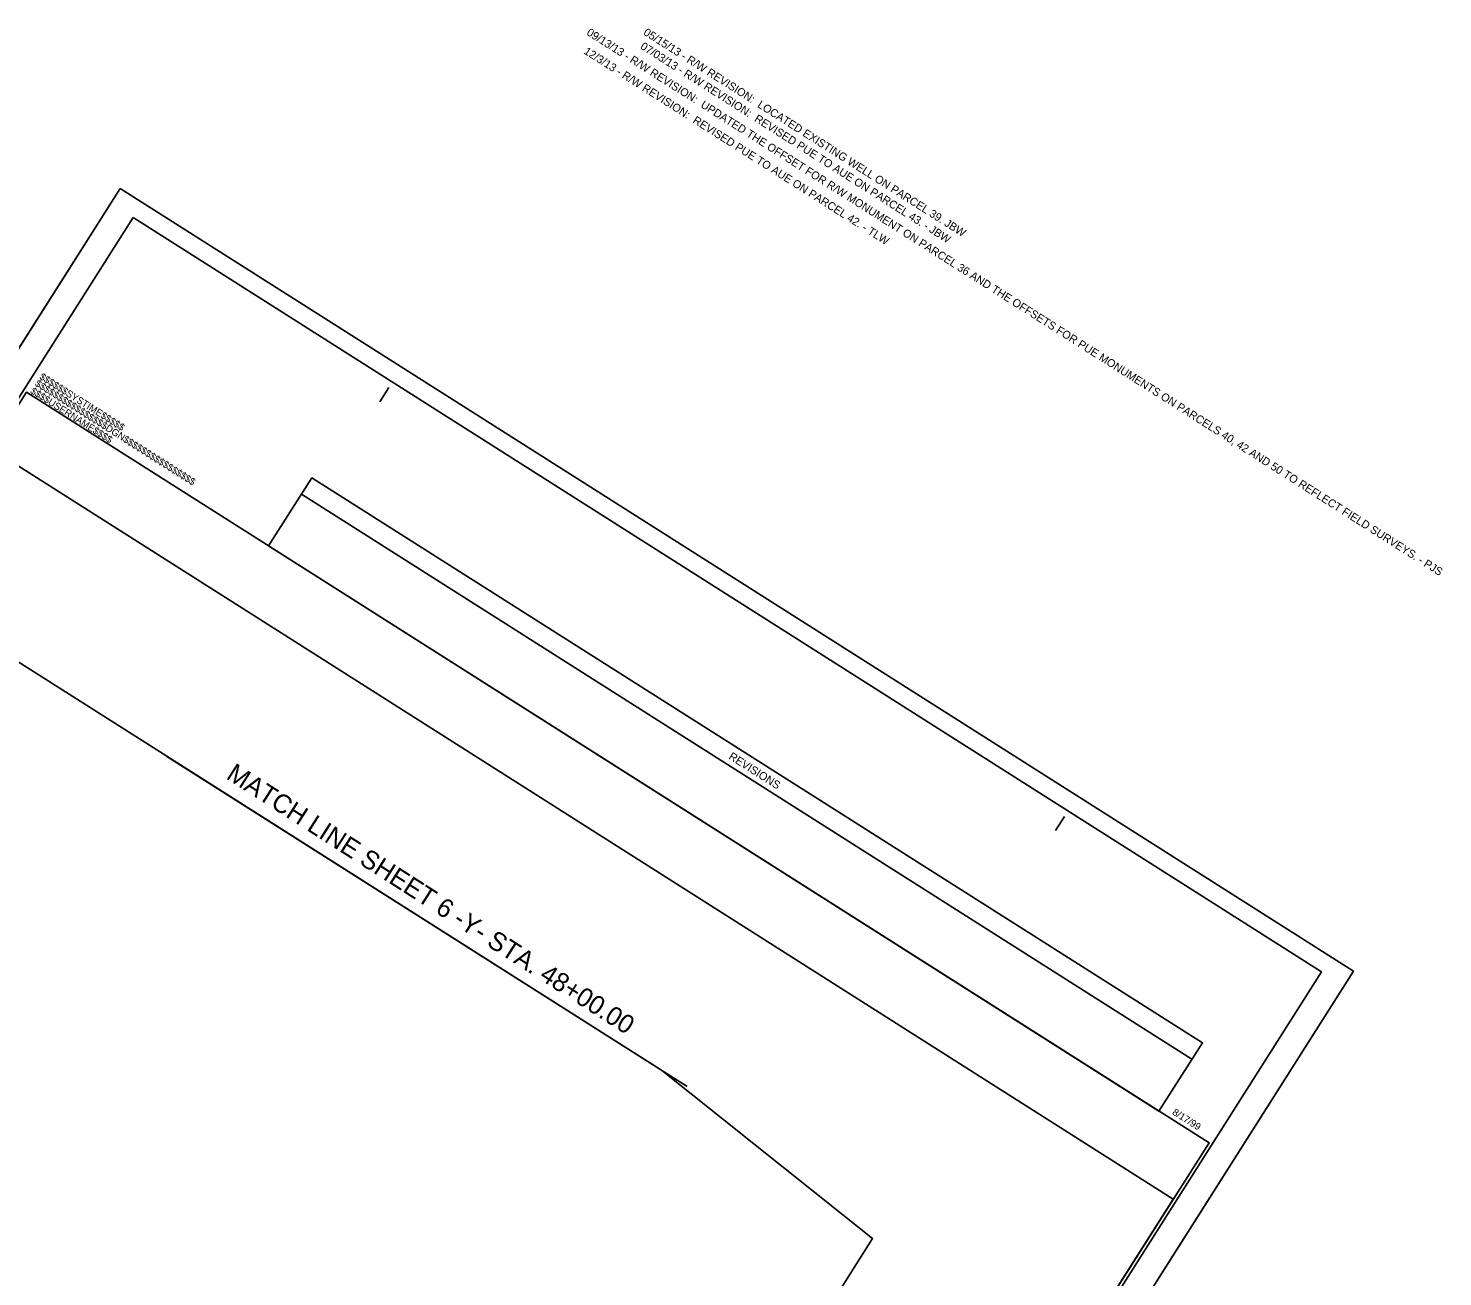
# Model space of a CAD drawing. Extents: x 1780138 to 1782093, y 811157 to 813450.
# Drawn here: x 1781033 to 1782093, y 812514 to 813450 of the extents above; entities that cross this region are included whole.
import ezdxf

# ---------------------------------------------------------------- set-up
doc = ezdxf.new("R2010")
doc.units = 0
for name, color, linetype in [('Prop Easement Aerial Utility', 7, 'Continuous'), ('Prop Easement Construction', 7, 'Continuous'), ('Prop Easement Construction Station Offsets', 7, 'Continuous'), ('Prop Easement Permanent Utility', 7, 'Continuous'), ('Prop Easement Temporary Drainage', 7, 'Continuous'), ('Prop Easement Temporary Utility', 7, 'Continuous'), ('Prop Easement Temporary Utility Station Offsets', 7, 'Continuous'), ('Prop ROW CA Lines', 7, 'Continuous'), ('Prop ROW Marker CELL', 7, 'Continuous'), ('Prop ROW Station Offsets', 7, 'Continuous')]:
    doc.layers.add(name, color=color, linetype=linetype)

msp = doc.modelspace()

# ---------------------------------------------------------------- linework, layer by layer
at = {"layer": 'Prop Easement Aerial Utility'}
for p, q in [((1781101.7, 813330), (1780199.6, 811908.6)), ((1782026.2, 812743.3), (1781101.7, 813330)), ((1781124.1, 811321.9), (1782026.2, 812743.3))]:
    msp.add_line(p, q, dxfattribs=at)
at = {"layer": 'Prop Easement Construction'}
msp.add_line((1781237.6, 813101), (1781905.2, 812677.4), dxfattribs=at)
msp.add_lwpolyline([(1781245.4, 813113.3), (1781913, 812689.7), (1781880.5, 812638.5), (1781213, 813062.2)], close=True, dxfattribs=at)
at = {"layer": 'Prop Easement Permanent Utility'}
msp.add_lwpolyline([(1781004.7, 813135.2), (1780254.5, 811953.1), (1780962.5, 811503.8), (1781063.9, 811663.6), (1781242.5, 811550.3), (1781891.2, 812572.6)], close=True, dxfattribs=at)
at = {"layer": 'Prop Easement Temporary Drainage'}
for p, q in [((1781303.1, 813180.9), (1781296.4, 813170.3)), ((1781809.7, 812859.4), (1781803, 812848.8)), ((1781918, 812614.8), (1781918, 812614.8))]:
    msp.add_line(p, q, dxfattribs=at)
for points in [[(1781114.3, 811348.3), (1781918, 812614.8), (1781031.5, 813177.4), (1780227.7, 811910.9)], [(1781031.5, 813177.4), (1781918, 812614.8), (1781221.5, 811517.2), (1781094.8, 811597.6), (1780987.6, 811428.7), (1780227.7, 811910.9)]]:
    msp.add_lwpolyline(points, close=True, dxfattribs=at)
at = {"layer": 'Prop Easement Temporary Utility'}
msp.add_lwpolyline([(1781918, 812614.8), (1781031.5, 813177.4), (1780227.7, 811910.9), (1780935.7, 811461.6), (1781063.9, 811663.6), (1781242.5, 811550.3)], close=True, dxfattribs=at)
at = {"layer": 'Prop Easement Temporary Utility Station Offsets'}
msp.add_line((1781136.7, 812904.4), (1781526.8, 812656.9), dxfattribs=at)
at = {"layer": 'Prop ROW CA Lines'}
msp.add_lwpolyline([(1781101.7, 813330), (1780199.6, 811908.6), (1781124.1, 811321.9), (1782026.2, 812743.3)], close=True, dxfattribs=at)
at = {"layer": 'Prop ROW Marker CELL'}
msp.add_lwpolyline([(1781516.2, 811981.6), (1781369.5, 812074.6), (1781637.4, 812498.2), (1781665.8, 812542.9), (1781507.5, 812669.1), (1780938.2, 813030.4), (1780382.1, 812154.2), (1780493.5, 812083.5), (1780398.6, 811861.6), (1781369, 811749.7)], close=True, dxfattribs=at)
at = {"layer": 'Prop ROW Station Offsets'}
msp.add_lwpolyline([(1781111.6, 813308.3), (1780218.9, 811901.7), (1781109.7, 811336.4), (1782002.3, 812743)], close=True, dxfattribs=at)

# ---------------------------------------------------------------- texts
at = {"layer": 'Prop Easement Construction'}
for s, p in [('09/13/13 - R/W REVISION:  UPDATED THE OFFSET FOR R/W MONUMENT ON PARCEL 36 AND THE OFFSETS FOR PUE MONUMENTS ON PARCELS 40, 42 AND 50 TO REFLECT FIELD SURVEYS. - PJS', (1781450.9, 813445.6)), ('05/15/13 - R/W REVISION:  LOCATED EXISTING WELL ON PARCEL 39. JBW ', (1781493.5, 813445.7)), ('07/03/13 - R/W REVISION:  REVISED PUE TO AUE ON PARCEL 43. - JBW ', (1781491.2, 813435.2)), ('12/3/13 - R/W REVISION:  REVISED PUE TO AUE ON PARCEL 42. - TLW ', (1781448.8, 813431.6)), ('REVISIONS', (1781557.4, 812902.9))]:
    msp.add_text(s, height=6, rotation=327.6004, dxfattribs=at).set_placement(p)
at = {"layer": 'Prop Easement Construction Station Offsets'}
msp.add_text('MATCH LINE SHEET 6 -Y- STA. 48+00.00', height=14, rotation=327.3551, dxfattribs=at).set_placement((1781180.5, 812888.2))
at = {"layer": 'Prop Easement Temporary Drainage'}
for s, p in [('$$$$$$$$$$$$$$$$DGN$$$$$$$$$$$$$$$$', (1781037.5, 813182.6)), ('$$$$$$SYSTIME$$$$$', (1781040.8, 813187.7)), ('$$$$USERNAME$$$$', (1781034, 813177)), ('8/17/99', (1781890, 812636.4))]:
    msp.add_text(s, height=5.25, rotation=327.6004, dxfattribs=at).set_placement(p)

doc.saveas('drawing.dxf')
